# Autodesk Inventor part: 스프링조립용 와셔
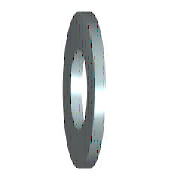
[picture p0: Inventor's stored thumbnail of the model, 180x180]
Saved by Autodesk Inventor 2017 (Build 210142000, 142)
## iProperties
IsCustomPart: 1
Created: 2012-02
Part Number: 스프링조립용 와셔
Material: 강철, 연강
Description: 평면 와셔
Document SubType Name: Modeling
Standard: KS B 1326
Designer: mduedu
Standards Organization: KS
Language: ko-KR
Size Designation: 12x24
Categories: <MemberInstance><Categories><Category DisplayName="조임쇠" InternalName="e4da775c-781d-43d5-af7c-5136215cf5a6" Mnemonic="FSTN"><Category DisplayName="와셔" InternalN
Density: 7.85 g/cm^3
Mass: 5.38854 g
Surface Area: 8.71478 cm^2
Volume: 0.686438 cm^3
Appearance: 강철
Author: mduedu
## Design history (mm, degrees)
sketch "스케치"
  geometry: C1 r 12 at (0, 0); C2 r 7 at (0, 0); 1 further point
  constraints: 2 centre point, 2 coincident
  dimensions: "d0" = 14 diameter of C2 (= SD1); "d1" = 24 diameter of C1 (= SD2)
extrude "본체" new body sketch "스케치" distance "d2" = 2.3 (= SD); taper "d3" = 0 deg
workaxis "Work Axis1"
workplane "Work Plane1"
body "Solid1"
other parameters: "SD1" = 14 [user parameter; used in 1 equation term], "SD2" = 24 [user parameter; used in 1 equation term], "SD" = 2.3 [user parameter; used in 1 equation term], "d4" = 0, "d5" = 0, "d6" = 0, "d7" = 0, "NND" = 12 [user parameter]
